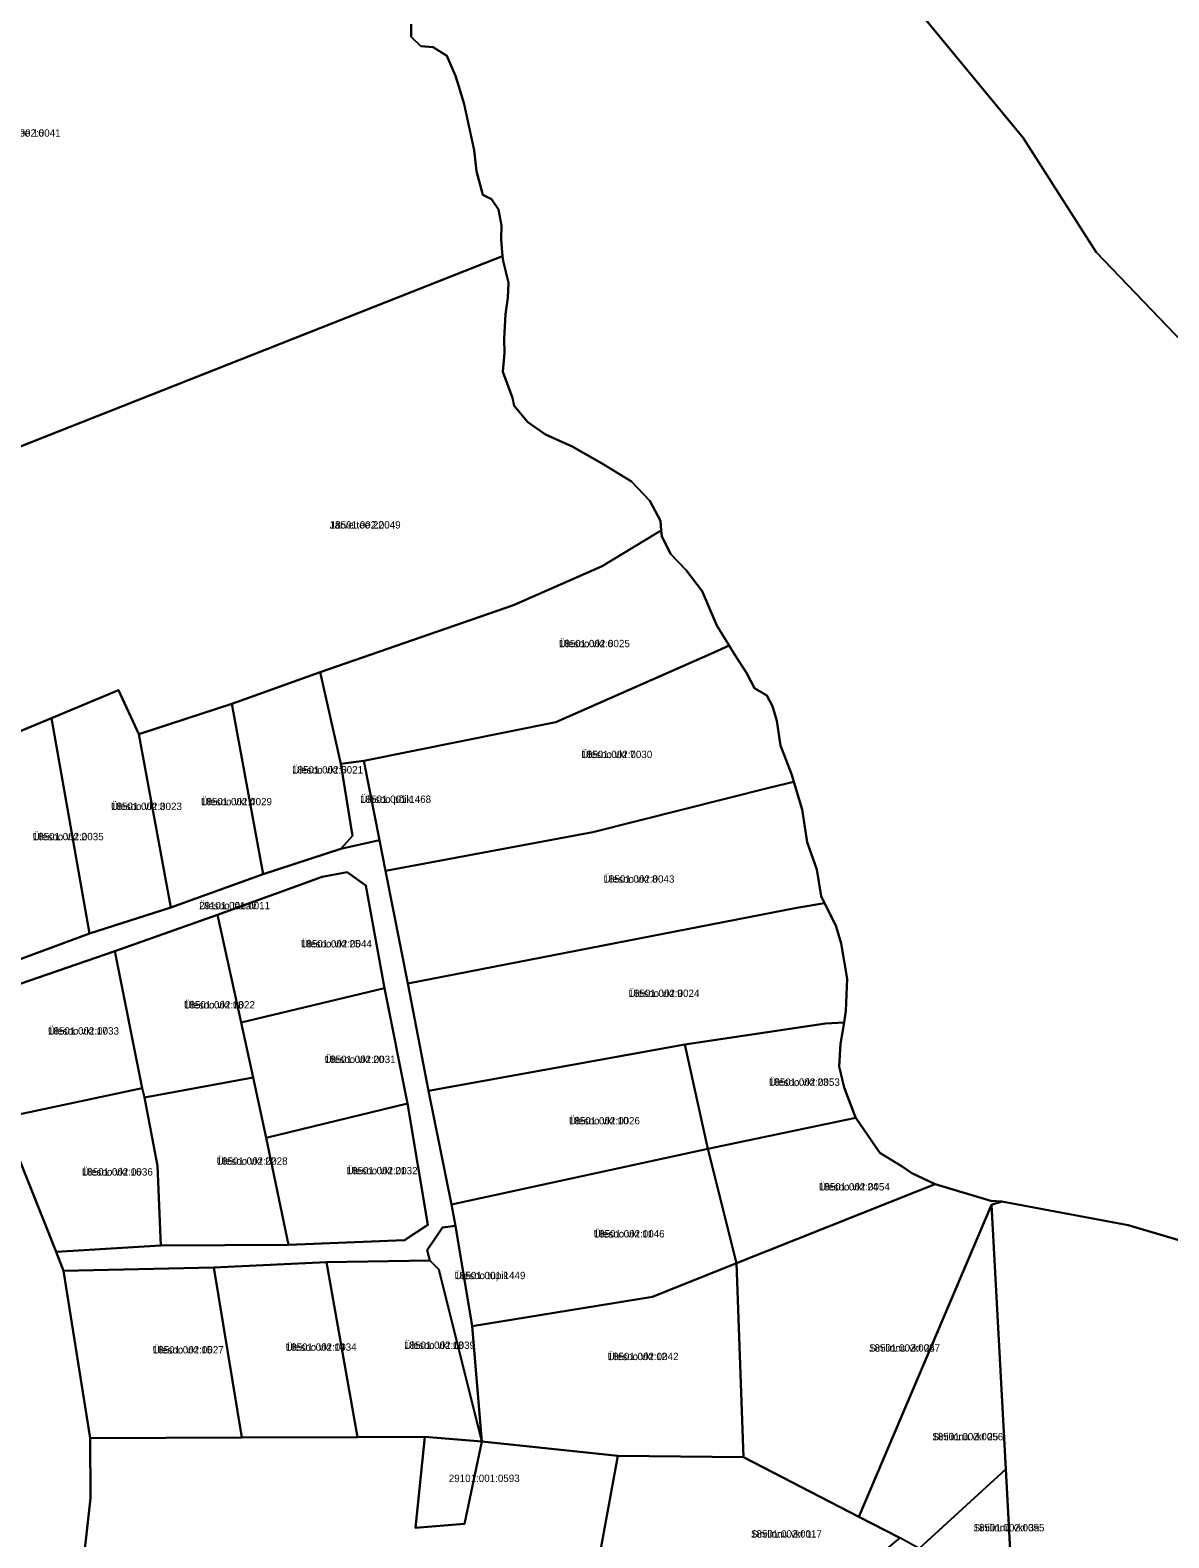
# Model space of a CAD drawing. Extents: x 660838 to 697091, y 6455678 to 6479886.
# Drawn here: x 665132 to 665364.7, y 6467450.2 to 6467758.1 of the extents above; entities that cross this region are included whole.
import ezdxf

# ---------------------------------------------------------------- set-up
doc = ezdxf.new("R2010")
doc.units = 0
for name, color, linetype in [('L_AADRESS', 7, 'Continuous'), ('PIIR', 7, 'Continuous'), ('TUNNUS', 7, 'Continuous')]:
    doc.layers.add(name, color=color, linetype=linetype)

msp = doc.modelspace()

# ---------------------------------------------------------------- linework, layer by layer
at = {"layer": 'PIIR'}
for points in [[(665000.57, 6467782.66), (665024.83, 6467737.25), (665056.35, 6467677.76), (665069.56, 6467652.33), (665084.77, 6467623.04), (665096.39, 6467600.67), (665114.12, 6467562.57), (665116.01, 6467558.56), (665126.4, 6467535.93), (665137.27, 6467508.61), (665138.8, 6467504.68), (665144.23, 6467470.51), (665144.3, 6467458.27), (665142.2, 6467439.35), (665136.57, 6467415.04), (665097.48, 6467299.63), (665077.59, 6467236.57), (665061.23, 6467178.15)], [(665209.85, 6467759.39), (665209.85, 6467756.74), (665211.78, 6467754.87), (665214.31, 6467754.69), (665217.15, 6467752.88), (665218.9, 6467748.78), (665219.88, 6467745.51), (665220.64, 6467742.99), (665222.69, 6467733.65), (665223.19, 6467729.31), (665224.48, 6467724.51), (665226.25, 6467723.63), (665227.7, 6467721.52), (665228.3, 6467718.2), (665228.24, 6467715.37), (665228.52, 6467711.98), (665223.43, 6467709.97), (665129.42, 6467672.9), (665115.86, 6467705.64), (665056.35, 6467677.76), (665024.83, 6467737.25), (665032.37, 6467740.11), (665110.11, 6467769.49)], [(665760.35, 6467769.93), (665735.4, 6467747.06), (665720.64, 6467733.34), (665688.51, 6467712.81), (665597.43, 6467672.04), (665572.12, 6467678.84), (665565.37, 6467680.54), (665539.45, 6467687.88), (665499.34, 6467698.97), (665492.19, 6467700.96), (665452.66, 6467711.93), (665433.95, 6467689.9), (665398.37, 6467647.99), (665382.11, 6467679.14), (665349.81, 6467712.79), (665334.9, 6467736.14), (665312.05, 6467763.79)], [(665312.05, 6467763.79), (665334.9, 6467736.14), (665349.81, 6467712.79), (665382.11, 6467679.14)], [(665394.19, 6467502.86), (665356.37, 6467514.03), (665330.51, 6467518.87), (665328.29, 6467518.97), (665316.9, 6467522.39), (665312.12, 6467524.63), (665310.17, 6467526.03), (665305.61, 6467528.8), (665300.72, 6467535.98), (665300.55, 6467536.22), (665298.32, 6467542.13), (665297.3, 6467546.47), (665297.6, 6467551.05), (665298.3, 6467555.41), (665298.69, 6467557.8), (665298.93, 6467564.32), (665297.67, 6467571.55), (665296.58, 6467575.23), (665294.31, 6467579.81), (665293.63, 6467581.2), (665292.75, 6467586.68), (665290.76, 6467592.29), (665289.74, 6467598.92), (665288.06, 6467604.58), (665287.63, 6467606.04), (665285.28, 6467612.01), (665284.56, 6467617.07), (665283.66, 6467620.03), (665282.51, 6467622.2), (665279.98, 6467623.7), (665278.35, 6467626.84), (665276, 6467630.52), (665274.82, 6467632.44), (665272.32, 6467636.49), (665269.31, 6467643.54), (665266, 6467647.82), (665264.23, 6467649.69), (665262.92, 6467651.08), (665261.06, 6467654.7), (665260.94, 6467655.91), (665260.75, 6467657.89), (665258.58, 6467661.99), (665254.85, 6467665.91), (665248.76, 6467669.71), (665242.73, 6467673.09), (665237.25, 6467675.56), (665233.69, 6467678.09), (665230.89, 6467681.37), (665230.52, 6467683.05), (665228.59, 6467688.36), (665228.9, 6467692.22), (665228.84, 6467695.05), (665229.14, 6467700.12), (665229.56, 6467703.43), (665229.74, 6467706.51), (665228.6, 6467711.03), (665228.52, 6467711.98), (665228.24, 6467715.37), (665228.3, 6467718.2), (665227.7, 6467721.52), (665226.25, 6467723.63), (665224.48, 6467724.51), (665223.19, 6467729.31), (665222.69, 6467733.65), (665220.64, 6467742.99), (665219.88, 6467745.51), (665218.9, 6467748.78), (665217.15, 6467752.88), (665214.31, 6467754.69), (665211.78, 6467754.87), (665209.85, 6467756.74), (665209.85, 6467759.39)], [(665129.42, 6467672.9), (665223.43, 6467709.97), (665228.52, 6467711.98), (665228.6, 6467711.03), (665229.74, 6467706.51), (665229.56, 6467703.43), (665229.14, 6467700.12), (665228.84, 6467695.05), (665228.9, 6467692.22), (665228.59, 6467688.36), (665230.52, 6467683.05), (665230.89, 6467681.37), (665233.69, 6467678.09), (665237.25, 6467675.56), (665242.73, 6467673.09), (665248.76, 6467669.71), (665254.85, 6467665.91), (665258.58, 6467661.99), (665260.75, 6467657.89), (665260.94, 6467655.91), (665259.73, 6467655.27), (665248.83, 6467648.66), (665230.77, 6467640.66), (665191.22, 6467626.96), (665173.16, 6467620.49), (665154.19, 6467614.3), (665150.02, 6467623.31), (665136.3, 6467617.56), (665120.87, 6467611.19)], [(665128.84, 6467567.98), (665144.11, 6467573.6), (665160.69, 6467578.94), (665179.56, 6467585.73), (665195.48, 6467590.92), (665203.34, 6467592.7), (665204.58, 6467586.43), (665209.16, 6467563.41), (665213.39, 6467541.49), (665218.09, 6467518.27), (665218.86, 6467513.86), (665216.2, 6467513.53), (665213.07, 6467508.89), (665213.65, 6467506.82), (665192.5, 6467506.45), (665169.5, 6467505.36), (665138.8, 6467504.68), (665137.27, 6467508.61), (665158.69, 6467509.87), (665184.78, 6467509.99), (665208.49, 6467510.98), (665213.27, 6467514.08), (665209.07, 6467538.86), (665204.38, 6467562.47), (665200.57, 6467583.41), (665196.75, 6467586.11), (665191.65, 6467585.16), (665170.27, 6467577.42), (665149.27, 6467570), (665116.01, 6467558.56)], [(665142.2, 6467439.35), (665144.3, 6467458.27), (665144.23, 6467470.51), (665175.24, 6467470.64), (665198.86, 6467470.75), (665212.64, 6467470.81), (665210.74, 6467452.2), (665220.74, 6467452.99), (665224.28, 6467469.85), (665252.04, 6467466.92), (665245.95, 6467433.49)]]:
    msp.add_lwpolyline(points, dxfattribs=at)
for points in [[(665239.39, 6467616.76), (665200.15, 6467608.88), (665195.45, 6467608.26), (665191.22, 6467626.96), (665230.77, 6467640.66), (665248.83, 6467648.66), (665259.73, 6467655.27), (665260.94, 6467655.91), (665261.06, 6467654.7), (665262.92, 6467651.08), (665264.23, 6467649.69), (665266, 6467647.82), (665269.31, 6467643.54), (665272.32, 6467636.49), (665274.82, 6467632.44), (665271.68, 6467631.04)], [(665246.97, 6467594.29), (665204.58, 6467586.43), (665203.34, 6467592.7), (665200.15, 6467608.88), (665239.39, 6467616.76), (665271.68, 6467631.04), (665274.82, 6467632.44), (665276, 6467630.52), (665278.35, 6467626.84), (665279.98, 6467623.7), (665282.51, 6467622.2), (665283.66, 6467620.03), (665284.56, 6467617.07), (665285.28, 6467612.01), (665287.63, 6467606.04), (665288.06, 6467604.58), (665283.17, 6467603.41)], [(665197.85, 6467593.58), (665195.48, 6467590.92), (665179.56, 6467585.73), (665173.16, 6467620.49), (665191.22, 6467626.96), (665195.45, 6467608.26)], [(665144.11, 6467573.6), (665136.3, 6467617.56), (665150.02, 6467623.31), (665154.19, 6467614.3), (665160.69, 6467578.94)], [(665160.69, 6467578.94), (665154.19, 6467614.3), (665173.16, 6467620.49), (665179.56, 6467585.73)], [(665128.84, 6467567.98), (665120.87, 6467611.19), (665136.3, 6467617.56), (665144.11, 6467573.6)], [(665197.85, 6467593.58), (665195.45, 6467608.26), (665200.15, 6467608.88), (665203.34, 6467592.7), (665195.48, 6467590.92)], [(665246.97, 6467594.29), (665283.17, 6467603.41), (665288.06, 6467604.58), (665289.74, 6467598.92), (665290.76, 6467592.29), (665292.75, 6467586.68), (665293.63, 6467581.2), (665294.31, 6467579.81), (665288.61, 6467578.84), (665209.16, 6467563.41), (665204.58, 6467586.43)], [(665191.65, 6467585.16), (665196.75, 6467586.11), (665200.57, 6467583.41), (665204.38, 6467562.47), (665175.1, 6467555.41), (665170.27, 6467577.42)], [(665294.31, 6467579.81), (665296.58, 6467575.23), (665297.67, 6467571.55), (665298.93, 6467564.32), (665298.69, 6467557.8), (665298.3, 6467555.41), (665294.47, 6467555.19), (665265.75, 6467550.94), (665213.39, 6467541.49), (665209.16, 6467563.41), (665288.61, 6467578.84)], [(665170.27, 6467577.42), (665175.1, 6467555.41), (665177.53, 6467544.18), (665155.36, 6467540.12), (665154.83, 6467542.04), (665149.27, 6467570)], [(665126.4, 6467535.93), (665116.01, 6467558.56), (665149.27, 6467570), (665154.83, 6467542.04)], [(665180.22, 6467531.85), (665177.53, 6467544.18), (665175.1, 6467555.41), (665204.38, 6467562.47), (665209.07, 6467538.86)], [(665265.75, 6467550.94), (665294.47, 6467555.19), (665298.3, 6467555.41), (665297.6, 6467551.05), (665297.3, 6467546.47), (665298.32, 6467542.13), (665300.55, 6467536.22), (665300.72, 6467535.98), (665298.73, 6467535.55), (665270.48, 6467529.59)], [(665270.48, 6467529.59), (665218.09, 6467518.27), (665213.39, 6467541.49), (665265.75, 6467550.94)], [(665158.02, 6467526.12), (665155.36, 6467540.12), (665177.53, 6467544.18), (665180.22, 6467531.85), (665184.78, 6467509.99), (665158.69, 6467509.87)], [(665137.27, 6467508.61), (665126.4, 6467535.93), (665154.83, 6467542.04), (665155.36, 6467540.12), (665158.02, 6467526.12), (665158.69, 6467509.87)], [(665209.07, 6467538.86), (665213.27, 6467514.08), (665208.49, 6467510.98), (665184.78, 6467509.99), (665180.22, 6467531.85)], [(665300.72, 6467535.98), (665305.61, 6467528.8), (665310.17, 6467526.03), (665312.12, 6467524.63), (665316.9, 6467522.39), (665313.62, 6467521.09), (665276.29, 6467506.27), (665270.48, 6467529.59), (665298.73, 6467535.55)], [(665276.29, 6467506.27), (665259.17, 6467499.37), (665222.32, 6467493.43), (665218.86, 6467513.86), (665218.09, 6467518.27), (665270.48, 6467529.59)], [(665316.9, 6467522.39), (665328.29, 6467518.97), (665330.51, 6467518.87), (665328.42, 6467518.21), (665301.31, 6467454.46), (665277.75, 6467466.64), (665276.29, 6467506.27), (665313.62, 6467521.09)], [(665328.42, 6467518.21), (665331.33, 6467464.22), (665313.66, 6467447.98), (665309.68, 6467450.13), (665301.31, 6467454.46)], [(665330.51, 6467518.87), (665356.37, 6467514.03), (665394.19, 6467502.86), (665414.94, 6467484.17), (665437.82, 6467485.16), (665459.92, 6467477.79), (665481.78, 6467473.68), (665493.71, 6467473.64), (665493.04, 6467465.8), (665476.27, 6467410.67), (665473.1, 6467411.54), (665425.3, 6467429.85), (665418.68, 6467429.61), (665400.36, 6467404.34), (665382.75, 6467413.36), (665361.82, 6467424.3), (665335.29, 6467437.06), (665332.7, 6467438.75), (665331.33, 6467464.22), (665328.42, 6467518.21)], [(665215.46, 6467504.97), (665213.65, 6467506.82), (665213.07, 6467508.89), (665216.2, 6467513.53), (665218.86, 6467513.86), (665222.32, 6467493.43), (665224.28, 6467469.85)], [(665175.24, 6467470.64), (665144.23, 6467470.51), (665138.8, 6467504.68), (665169.5, 6467505.36)], [(665175.24, 6467470.64), (665169.5, 6467505.36), (665192.5, 6467506.45), (665198.86, 6467470.75)], [(665212.64, 6467470.81), (665198.86, 6467470.75), (665192.5, 6467506.45), (665213.65, 6467506.82), (665215.46, 6467504.97), (665224.28, 6467469.85)], [(665277.75, 6467466.64), (665252.04, 6467466.92), (665224.28, 6467469.85), (665222.32, 6467493.43), (665259.17, 6467499.37), (665276.29, 6467506.27)], [(665220.74, 6467452.99), (665210.74, 6467452.2), (665212.64, 6467470.81), (665224.28, 6467469.85)], [(665277.75, 6467466.64), (665301.31, 6467454.46), (665309.68, 6467450.13), (665296.9, 6467439.5), (665245.95, 6467433.49), (665252.04, 6467466.92)], [(665331.33, 6467464.22), (665332.7, 6467438.75), (665314.93, 6467447.44), (665313.66, 6467447.98)]]:
    msp.add_lwpolyline(points, close=True, dxfattribs=at)

# ---------------------------------------------------------------- texts
at = {"layer": 'L_AADRESS'}
for s, p in [('Järve tee 16', (665123.69, 6467736.38)), ('Järve tee 22', (665193.18, 6467656.33)), ('Ülesoo vkt 6', (665240.02, 6467632.09)), ('Ülesoo vkt 7', (665244.6, 6467609.44)), ('Ülesoo vkt 5', (665185.5, 6467606.29)), ('Ülesoo vkt 3', (665148.49, 6467598.84)), ('Ülesoo vkt 4', (665166.88, 6467599.8)), ('Ülesoo põik', (665199.4, 6467600.29)), ('Ülesoo vkt 2', (665132.49, 6467592.66)), ('Ülesoo vkt 8', (665249.12, 6467583.99)), ('Ülesoo tänav', (665166.49, 6467578.56)), ('Ülesoo vkt 25', (665187.3, 6467570.76)), ('Ülesoo vkt 18', (665163.4, 6467558.29)), ('Ülesoo vkt 9', (665254.24, 6467560.65)), ('Ülesoo vkt 17', (665135.62, 6467552.96)), ('Ülesoo vkt 20', (665192.15, 6467547.16)), ('Ülesoo vkt 23', (665282.93, 6467542.5)), ('Ülesoo vkt 10', (665242.08, 6467534.61)), ('Ülesoo vkt 16', (665142.54, 6467524.16)), ('Ülesoo vkt 22', (665170.07, 6467526.37)), ('Ülesoo vkt 21', (665196.64, 6467524.42)), ('Ülesoo vkt 24', (665293.15, 6467521.12)), ('Ülesoo vkt 11', (665247.12, 6467511.51)), ('Ülesoo tupik', (665218.68, 6467503)), ('Ülesoo vkt 15', (665157.02, 6467487.82)), ('Ülesoo vkt 14', (665184.18, 6467488.37)), ('Ülesoo vkt 13', (665208.39, 6467488.76)), ('Sinilinnu vkt 24', (665303.4, 6467488.2)), ('Ülesoo vkt 12', (665249.96, 6467486.46)), ('Sinilinnu vkt 25', (665316.32, 6467470.09)), ('Sinilinnu vkt 1', (665279.27, 6467450.21)), ('Sinilinnu vkt 3a', (665324.74, 6467451.49))]:
    msp.add_text(s, height=1.5, dxfattribs=at).set_placement(p)
at = {"layer": 'TUNNUS'}
for s, p in [('18501:002:0041', (665123.69, 6467736.38)), ('18501:002:0049', (665193.18, 6467656.33)), ('18501:002:0025', (665240.02, 6467632.09)), ('18501:002:0030', (665244.6, 6467609.44)), ('18501:002:0021', (665185.5, 6467606.29)), ('18501:002:0023', (665148.49, 6467598.84)), ('18501:002:0029', (665166.88, 6467599.8)), ('18501:001:1468', (665199.4, 6467600.29)), ('18501:002:0035', (665132.49, 6467592.66)), ('18501:002:0043', (665249.12, 6467583.99)), ('29101:001:0011', (665166.49, 6467578.56)), ('18501:002:0044', (665187.3, 6467570.76)), ('18501:002:0022', (665163.4, 6467558.29)), ('18501:002:0024', (665254.24, 6467560.65)), ('18501:002:0033', (665135.62, 6467552.96)), ('18501:002:0031', (665192.15, 6467547.16)), ('18501:002:0053', (665282.93, 6467542.5)), ('18501:002:0026', (665242.08, 6467534.61)), ('18501:002:0036', (665142.54, 6467524.16)), ('18501:002:0028', (665170.07, 6467526.37)), ('18501:002:0032', (665196.64, 6467524.42)), ('18501:002:0054', (665293.15, 6467521.12)), ('18501:002:0046', (665247.12, 6467511.51)), ('18501:001:1449', (665218.68, 6467503)), ('18501:002:0027', (665157.02, 6467487.82)), ('18501:002:0034', (665184.18, 6467488.37)), ('18501:002:0039', (665208.39, 6467488.76)), ('18501:002:0057', (665303.4, 6467488.2)), ('18501:002:0042', (665249.96, 6467486.46)), ('18501:002:0056', (665316.32, 6467470.09)), ('29101:001:0593', (665217.51, 6467461.57)), ('18501:002:0055', (665324.74, 6467451.49)), ('18501:002:0017', (665279.27, 6467450.21))]:
    msp.add_text(s, height=1.5, dxfattribs=at).set_placement(p)

doc.saveas('drawing.dxf')
